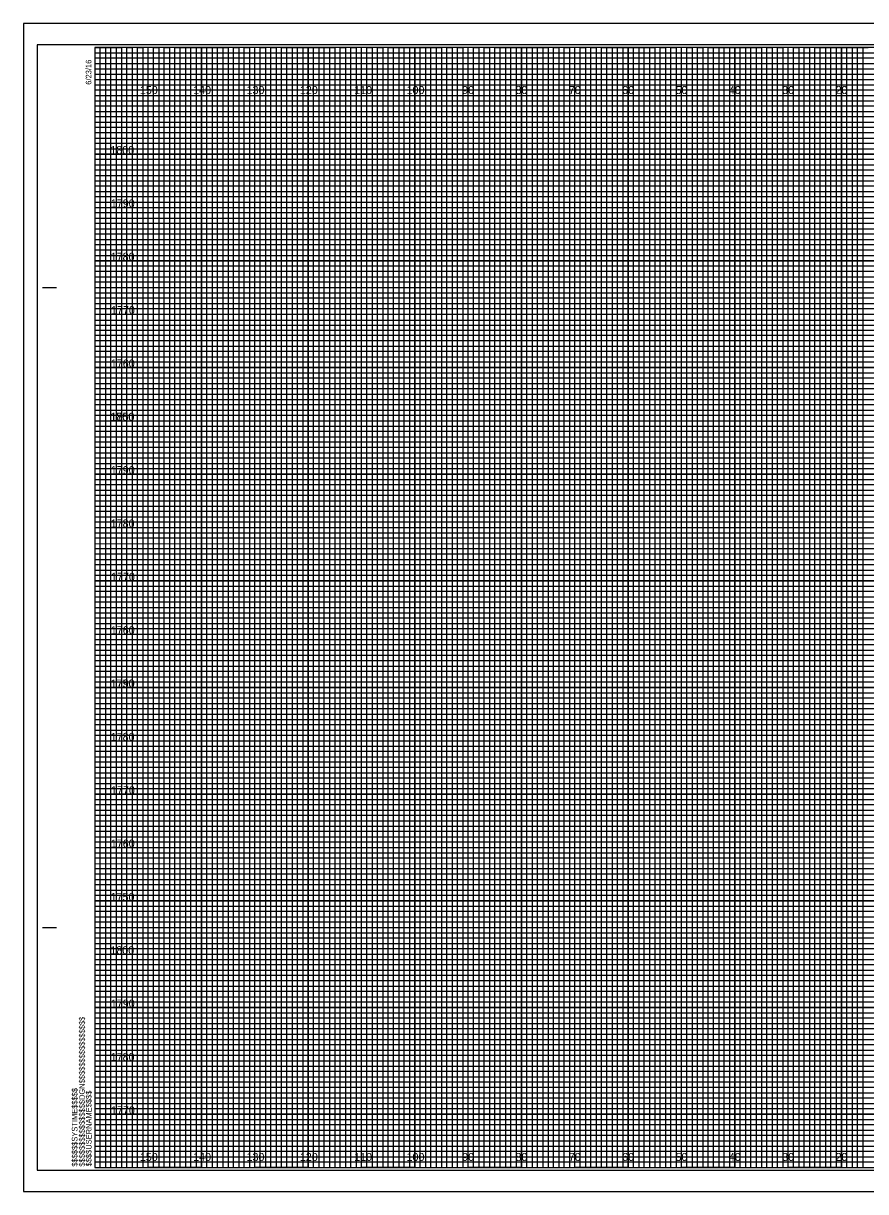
# Model space of a CAD drawing. Extents: x -13 to 323, y -5 to 874.
# Drawn here: x -13.4 to 144.5, y -4.5 to 214.5 of the extents above; entities that cross this region are included whole.
import ezdxf

# ---------------------------------------------------------------- set-up
doc = ezdxf.new("R2010")
doc.units = 0
for name, color, linetype in [('Prop XS Earthwork Shape', 7, 'Continuous'), ('Raster_Level_0', 7, 'Continuous'), ('Scratch_Level_3', 7, 'Continuous'), ('Sheet Cross Section CELL', 7, 'Continuous'), ('Sheet Cross Section Grid Middle CELL', 7, 'Continuous'), ('Sheet Cross Section Grid Minor 1 CELL', 7, 'Continuous'), ('Sheet Cross Section Grid Minor 2 CELL', 7, 'Continuous'), ('Sheet Cutting Line CELL', 7, 'Continuous'), ('Sheet DOT Grid CELL', 7, 'Continuous'), ('Sheet Plot Border Inside CELL', 7, 'Continuous'), ('Sheet Plot Border Outside CELL', 7, 'Continuous')]:
    doc.layers.add(name, color=color, linetype=linetype)

msp = doc.modelspace()

# ---------------------------------------------------------------- linework, layer by layer
at = {"layer": 'Prop XS Earthwork Shape'}
for p, q in [((10, 210), (0, 210)), ((10, 0), (10, 210)), ((30, 210), (20, 210)), ((20, 210), (20, 0)), ((30, 0), (30, 210)), ((50, 210), (40, 210)), ((40, 210), (40, 0)), ((50, 0), (50, 210)), ((70, 210), (60, 210)), ((60, 210), (60, 0)), ((70, 0), (70, 210)), ((90, 210), (80, 210)), ((80, 210), (80, 0)), ((90, 0), (90, 210)), ((110, 210), (100, 210)), ((100, 210), (100, 0)), ((110, 0), (110, 210)), ((130, 210), (120, 210)), ((120, 210), (120, 0)), ((130, 0), (130, 210)), ((150, 210), (140, 210)), ((140, 210), (140, 0)), ((20, 0), (10, 0)), ((40, 0), (30, 0)), ((60, 0), (50, 0)), ((80, 0), (70, 0)), ((100, 0), (90, 0)), ((120, 0), (110, 0)), ((140, 0), (130, 0))]:
    msp.add_line(p, q, dxfattribs=at)
for points in [[(0, 200), (320, 200), (320, 190), (0, 190)], [(0, 180), (320, 180), (320, 170), (0, 170)], [(0, 160), (320, 160), (320, 150), (0, 150)], [(0, 140), (320, 140), (320, 130), (0, 130)], [(0, 120), (320, 120), (320, 110), (0, 110)], [(0, 100), (320, 100), (320, 90), (0, 90)], [(0, 80), (320, 80), (320, 70), (0, 70)], [(0, 60), (320, 60), (320, 50), (0, 50)], [(0, 40), (320, 40), (320, 30), (0, 30)], [(0, 20), (320, 20), (320, 10), (0, 10)]]:
    msp.add_lwpolyline(points, dxfattribs=at)
at = {"layer": 'Sheet Cross Section CELL'}
for p, q in [((-9.8, 165), (-7.3, 165)), ((-9.7, 165), (-7.2, 165)), ((-9.8, 45), (-7.3, 45)), ((-9.7, 45), (-7.2, 45)), ((0, 0), (0, 0)), ((0, 0), (0, 0)), ((0, 0), (0, 0)), ((0, 0), (0, 0)), ((0, 0), (0, 0)), ((0, 0), (0, 0)), ((0, 0), (0, 0))]:
    msp.add_line(p, q, dxfattribs=at)
msp.add_lwpolyline([(320, 210), (0, 210), (0, 0), (320, 0)], close=True, dxfattribs=at)
at = {"layer": 'Sheet Cross Section Grid Middle CELL'}
for points in [[(0, 210), (5, 210), (5, 0), (15, 0), (15, 210), (25, 210), (25, 0), (35, 0), (35, 210), (45, 210), (45, 0), (55, 0), (55, 210), (65, 210), (65, 0), (75, 0), (75, 210), (85, 210), (85, 0), (95, 0), (95, 210), (105, 210), (105, 0), (115, 0), (115, 210), (125, 210), (125, 0), (135, 0), (135, 210), (145, 210)], [(0, 205), (275, 205)], [(0, 185), (320, 185), (320, 195), (0, 195)], [(0, 165), (320, 165), (320, 175), (0, 175)], [(0, 145), (320, 145), (320, 155), (0, 155)], [(0, 125), (320, 125), (320, 135), (0, 135)], [(0, 105), (320, 105), (320, 115), (0, 115)], [(0, 85), (320, 85), (320, 95), (0, 95)], [(0, 65), (320, 65), (320, 75), (0, 75)], [(0, 45), (320, 45), (320, 55), (0, 55)], [(0, 25), (320, 25), (320, 35), (0, 35)], [(0, 5), (320, 5), (320, 15), (0, 15)]]:
    msp.add_lwpolyline(points, dxfattribs=at)
at = {"layer": 'Sheet Cross Section Grid Minor 1 CELL'}
for p, q in [((0, 209), (260, 209)), ((260, 207.98), (0, 207.98)), ((0, 207.98), (0, 207)), ((0, 207), (260, 207)), ((260, 205.89), (0, 205.89)), ((0, 205.89), (0, 204)), ((0, 204), (320, 204))]:
    msp.add_line(p, q, dxfattribs=at)
for points in [[(0, 203), (270, 203), (320, 203), (320, 202), (0, 202)], [(0, 201), (320, 201), (320, 199), (0, 199)], [(0, 198), (320, 198), (320, 197), (0, 196.98)], [(0, 196), (320, 196), (320, 194), (0, 194)], [(0, 193), (320, 193), (320, 192), (0, 192)], [(0, 191), (320, 191), (320, 189), (0, 189)], [(0, 188), (320, 188), (320, 187), (0, 187)], [(0, 186), (320, 186), (320, 184), (0, 184)], [(0, 183), (320, 183), (320, 182), (0, 182)], [(0, 181), (320, 181), (320, 179), (0, 179)], [(0, 178), (320, 178), (320, 177), (0, 177)], [(0, 176), (320, 176), (320, 173.95), (320, 173), (320, 172), (0, 172)], [(0, 174), (320, 174), (320, 173), (0, 173)], [(0, 171), (320, 171), (320, 169), (0, 169.03)], [(0, 169.03), (320, 169), (320, 168), (0, 168)], [(0, 167), (320, 167), (320, 166), (0, 166)], [(0, 164), (320, 164), (320, 163), (0, 163)], [(0, 162), (320, 162), (320, 161), (0, 161)], [(-0.07, 158.89), (320, 158.89), (320, 157.88), (-0.07, 157.88)], [(0, 157), (320, 157), (320, 156), (0, 156)], [(0, 154), (320, 154), (320, 153), (0, 153)], [(0, 152), (320, 152), (320, 151), (0, 151)], [(0, 149), (320, 149), (320, 148), (0, 148)], [(0, 147), (320, 147), (320, 146), (0, 146)], [(0, 144), (320, 144), (320, 143), (0, 143)], [(0, 142), (320, 142), (320, 141), (0, 141)], [(0, 139), (320, 139), (319.99, 137.98), (0, 138)], [(0, 137), (320, 137), (320, 136), (0, 136)], [(0, 134), (320, 134), (320, 133), (0, 133)], [(0, 132), (320, 132), (320, 131), (0, 131)], [(0, 129), (320, 129), (320, 128), (0, 128)], [(0, 127), (320, 127), (320, 126), (0, 126)], [(0, 124), (320, 124), (320, 123), (0, 123)], [(0, 122), (320, 122), (320, 121), (0, 121)], [(0, 119), (320, 119), (320, 118), (0, 118)], [(0, 116.99), (320.07, 116.91), (320, 116), (0, 116)], [(0, 114), (320, 114), (320, 113), (0, 113)], [(0, 112), (320, 112), (320, 111), (0, 111)], [(0, 109), (320, 109), (320, 108), (0, 108)], [(0, 107), (320, 107), (320, 106), (0, 106)], [(0, 104), (320, 104), (320, 103), (0, 103)], [(0, 102), (320, 102), (320, 101), (0, 101)], [(0, 99), (320, 99), (320, 98), (0, 98)], [(0, 97), (320, 97), (320, 96), (0, 96)], [(0, 94), (320, 94), (320, 93), (0, 93)], [(0, 92), (320, 92), (320, 91), (0, 91)], [(0, 89), (320, 89), (320, 88), (0, 88)], [(0, 87), (320, 87), (320, 86), (0, 86)], [(0, 84), (320, 84), (320, 83), (0, 83)], [(0, 82), (320, 82), (320, 81), (0, 81)], [(0, 79), (320, 79), (319.99, 77.98), (0, 78)], [(0, 77), (320, 77), (320, 76), (0, 76)], [(0, 74), (320, 74), (320, 73), (0, 73)], [(0, 72), (320, 72), (320, 71), (0, 71)], [(0, 69), (320, 69), (320, 68), (0, 68)], [(0, 67), (320, 67), (320, 66), (0, 66)], [(0, 64), (320, 64), (320, 63), (0, 63)], [(0, 62), (320, 62), (320, 61), (0, 61)], [(0, 59), (320, 59), (320, 58), (0, 58)], [(0, 56.99), (320.07, 56.91), (320, 56), (0, 56)], [(0, 54), (320, 54), (320, 53), (0, 53)], [(0, 52), (320, 52), (320, 51), (0, 51)], [(0, 49), (320, 49), (320, 48), (0, 48)], [(0, 47), (320, 47), (320, 46), (0, 46)], [(0, 44), (320, 44), (320, 43), (0, 43)], [(0, 42), (320, 42), (320, 41), (0, 41)], [(0, 39), (320, 39), (320, 38), (0, 38)], [(0, 37), (320, 37), (320, 36), (0, 36)], [(0, 34), (320, 34), (320, 33), (0, 33)], [(0, 32), (320, 32), (320, 31), (0, 31)], [(0, 29), (320, 29), (320, 28), (0, 28)], [(0, 27), (320, 27), (320, 26), (0, 26)], [(0, 24), (320, 24), (320, 23), (0, 23)], [(0, 22), (320, 22), (320, 21), (0, 21)], [(0, 19), (320, 19), (320, 18), (0, 18)], [(0, 17), (320, 17), (320, 16), (0, 16)], [(0, 14), (320, 14), (320, 13), (0, 13)], [(0, 12), (320, 12), (320, 11), (0, 11)], [(0, 9), (320, 9), (320, 8), (0, 8)], [(0, 7), (320, 7), (320, 6), (0, 6)], [(0, 4), (320, 4), (320, 3), (0, 3)], [(0, 2), (320, 2), (320, 1), (0, 1)]]:
    msp.add_lwpolyline(points, dxfattribs=at)
at = {"layer": 'Sheet Cross Section Grid Minor 2 CELL'}
for points in [[(0, 0), (1, 0), (1, 210), (2, 210), (2, 0)], [(2, 0), (3, 0), (3, 210), (4, 210), (4, 0)], [(5, 0), (6, 0), (6, 210), (7, 210), (7, 0)], [(7, 0), (8, 0), (8, 210), (9, 210), (9, 0)], [(10, 0), (11, 0), (11, 210), (12, 210), (12, 0)], [(12, 0), (13, 0), (13, 210), (14, 210), (14, 0)], [(15, 0), (16, 0), (16, 210), (17, 210), (17, 0)], [(17, 0), (18, 0), (18, 210), (19, 210), (19, 0)], [(20, 0), (21, 0), (21, 210), (22, 210), (22, 0)], [(22, 0), (23, 0), (23, 210), (24, 210), (24, 0)], [(25, 0), (26, 0), (26, 210), (27, 210), (27, 0)], [(27, 0), (28, 0), (28, 210), (29, 210), (29, 0)], [(30, 0), (31, 0), (31, 210), (32, 210), (32, 0)], [(32, 0), (33, 0), (33, 210), (34, 210), (34, 0)], [(35, 0), (36, 0), (36, 210), (37, 210), (37, 0)], [(37, 0), (38, 0), (38, 210), (39, 210), (39, 0)], [(40, 0), (41, 0), (41, 210), (42, 210), (42, 0)], [(42, 0), (43, 0), (43, 210), (44, 210), (44, 0)], [(45, 0), (46, 0), (46, 210), (47, 210), (47, 0)], [(47, 0), (48, 0), (48, 210), (49, 210), (49, 0)], [(50, 0), (51, 0), (51, 210), (52, 210), (52, 0)], [(52, 0), (53, 0), (53, 210), (54, 210), (54, 0)], [(55, 0), (56, 0), (56, 210), (57, 210), (57, 0)], [(57, 0), (58, 0), (58, 210), (59, 210), (59, 0)], [(60, 0), (61, 0), (61, 210), (62, 210), (62, 0)], [(62, 0), (63, 0), (63, 210), (64, 210), (64, 0)], [(65, 0), (66, 0), (66, 210), (67, 210), (67, 0)], [(67, 0), (68, 0), (68, 210), (69, 210), (69, 0)], [(70, 0), (71, 0), (71, 210), (72, 210), (72, 0)], [(72, 0), (73, 0), (73, 210), (74, 210), (74, 0)], [(75, 0), (76, 0), (76, 210), (77, 210), (77, 0)], [(77, 0), (78, 0), (78, 210), (79, 210), (79, 0)], [(80, 0), (81, 0), (81, 210), (82, 210), (82, 0)], [(82, 0), (83, 0), (83, 210), (84, 210), (84, 0)], [(85, 0), (86, 0), (86, 210), (87, 210), (87, 0)], [(87, 0), (88, 0), (88, 210), (89, 210), (89, 0)], [(90, 0), (91, 0), (91, 210), (92, 210), (92, 0)], [(92, 0), (93, 0), (93, 210), (94, 210), (94, 0)], [(95, 0), (96, 0), (96, 210), (97, 210), (97, 0)], [(97, 0), (98, 0), (98, 210), (99, 210), (99, 0)], [(100, 0), (101, 0), (101, 210), (102, 210), (102, 0)], [(102, 0), (103, 0), (103, 210), (104, 210), (104, 0)], [(105, 0), (106, 0), (106, 210), (107, 210), (107, 0)], [(107, 0), (108, 0), (108, 210), (109, 210), (109, 0)], [(110, 0), (111, 0), (111, 210), (112, 210), (112, 0)], [(112, 0), (113, 0), (113, 210), (114, 210), (114, 0)], [(115, 0), (116, 0), (116, 210), (117, 210), (117, 0)], [(117, 0), (118, 0), (118, 210), (119, 210), (119, 0)], [(120, 0), (121, 0), (121, 210), (122, 210), (122, 0)], [(122, 0), (123, 0), (123, 210), (124, 210), (124, 0)], [(125, 0), (126, 0), (126, 210), (127, 210), (127, 0)], [(127, 0), (128, 0), (128, 210), (129, 210), (129, 0)], [(130, 0), (131, 0), (131, 210), (132, 210), (132, 0)], [(132, 0), (133, 0), (133, 210), (134, 210), (134, 0)], [(135, 0), (136, 0), (136, 210), (137, 210), (137, 0)], [(137, 0), (138, 0), (138, 210), (139, 210), (139, 0)], [(140, 0), (141, 0), (141, 210), (142, 210), (142, 0)], [(142, 0), (143, 0), (143, 210), (144, 210), (144, 0)]]:
    msp.add_lwpolyline(points, dxfattribs=at)
at = {"layer": 'Sheet Cutting Line CELL'}
for p, q in [((323.3, 214.5), (-13.4, 214.5)), ((-13.4, 214.5), (-13.4, -4.5)), ((-13.4, -4.5), (323.3, -4.5))]:
    msp.add_line(p, q, dxfattribs=at)
at = {"layer": 'Sheet DOT Grid CELL'}
for p, q in [((10, 0), (10, 210)), ((20, 0), (20, 210)), ((30, 0), (30, 210)), ((40, 0), (40, 210)), ((50, 0), (50, 210)), ((60, 0), (60, 210)), ((70, 0), (70, 210)), ((80, 0), (80, 210)), ((90, 0), (90, 210)), ((100, 0), (100, 210)), ((110, 0), (110, 210)), ((120, 0), (120, 210)), ((130, 0), (130, 210)), ((140, 0), (140, 210)), ((0, 200), (320, 200)), ((0, 190), (320, 190)), ((0, 180), (320, 180)), ((0, 170), (320, 170)), ((0, 160), (320, 160)), ((0, 150), (320, 150)), ((0, 140), (320, 140)), ((0, 130), (320, 130)), ((0, 120), (320, 120)), ((0, 110), (320, 110)), ((0, 100), (320, 100)), ((0, 90), (320, 90)), ((0, 80), (320, 80)), ((0, 70), (320, 70)), ((0, 60), (320, 60)), ((0, 50), (320, 50)), ((0, 40), (320, 40)), ((0, 30), (320, 30)), ((0, 20), (320, 20)), ((0, 10), (320, 10))]:
    msp.add_line(p, q, dxfattribs=at)
at = {"layer": 'Sheet Plot Border Inside CELL'}
msp.add_lwpolyline([(-10.8, -0.5), (322.4, -0.5), (322.4, 210.5), (-10.8, 210.5)], close=True, dxfattribs=at)
at = {"layer": 'Sheet Plot Border Outside CELL'}
msp.add_lwpolyline([(-13.4, -4.5), (323.3, -4.5), (323.3, 214.5), (-13.4, 214.5)], close=True, dxfattribs=at)

# ---------------------------------------------------------------- texts
at = {"layer": 'Raster_Level_0'}
for s, p in [('150', (8.44, 201.25)), ('140', (18.44, 201.25)), ('130', (28.44, 201.25)), ('120', (38.44, 201.25)), ('110', (48.62, 201.25)), ('100', (58.44, 201.25)), ('90', (68.86, 201.25)), ('80', (78.86, 201.25)), ('70', (88.86, 201.25)), ('60', (98.86, 201.25)), ('50', (108.86, 201.25)), ('40', (118.86, 201.25)), ('30', (128.86, 201.25)), ('20', (138.86, 201.25)), ('150', (8.44, 1.25)), ('140', (18.44, 1.25)), ('130', (28.44, 1.25)), ('120', (38.44, 1.25)), ('110', (48.62, 1.25)), ('100', (58.44, 1.25)), ('90', (68.86, 1.25)), ('80', (78.86, 1.25)), ('70', (88.86, 1.25)), ('60', (98.86, 1.25)), ('50', (108.86, 1.25)), ('40', (118.86, 1.25)), ('30', (128.86, 1.25)), ('20', (138.86, 1.25))]:
    msp.add_text(s, height=1.5, dxfattribs=at).set_placement(p)
at = {"layer": 'Scratch_Level_3'}
for s, p in [('1800', (2.92, 190)), ('1790', (3, 180)), ('1780', (2.98, 170)), ('1770', (3.04, 160)), ('1760', (3, 150)), ('1800', (2.92, 140)), ('1750', (2.96, 140)), ('1790', (3, 130)), ('1780', (2.98, 120)), ('1770', (3.04, 110)), ('1760', (3, 100)), ('1750', (2.96, 90)), ('1790', (3, 90)), ('1780', (2.98, 80)), ('1770', (3.04, 70)), ('1760', (3, 60)), ('1750', (2.96, 50)), ('1800', (2.92, 40)), ('1790', (3, 30)), ('1780', (2.98, 20)), ('1770', (3.04, 10))]:
    msp.add_text(s, height=1.5, dxfattribs=at).set_placement(p)
at = {"layer": 'Sheet Cross Section CELL'}
for s, p in [('6/23/16', (-0.65, 203)), ('$$$$$$$$$$$$$$$$DGN$$$$$$$$$$$$$$$$', (-1.88, 0.18)), ('$$$$$$SYSTIME$$$$$', (-3.26, 0.18)), ('$$$$USERNAME$$$$', (-0.62, 0.23))]:
    msp.add_text(s, height=1.05, rotation=90, dxfattribs=at).set_placement(p)

doc.saveas('drawing.dxf')
